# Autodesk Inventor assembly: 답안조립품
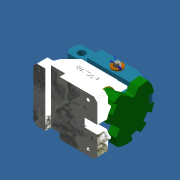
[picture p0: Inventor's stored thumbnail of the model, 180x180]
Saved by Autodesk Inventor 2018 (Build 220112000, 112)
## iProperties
Created: 2022-08
Part Number: 답안조립품
Material: 일반
Document SubType Name: Assembly
Designer: home
Author: home
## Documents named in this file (8)
- C:\Users\kimgi\Desktop\720806V1009\답안조립품.iam
- C:\Users\kimgi\Desktop\720806V1009\본체.ipt
- C:\Users\kimgi\Desktop\720806V1009\부시.ipt
- C:\Users\kimgi\Desktop\720806V1009\분할축.ipt
- C:\Users\kimgi\Desktop\720806V1009\분할대.ipt
- C:\Users\kimgi\Desktop\720806V1009\와셔.ipt
- C:\Users\kimgi\Desktop\720806V1009\클레비스핀.ipt
- C:\Users\kimgi\Desktop\720806V1009\분할핀.ipt
